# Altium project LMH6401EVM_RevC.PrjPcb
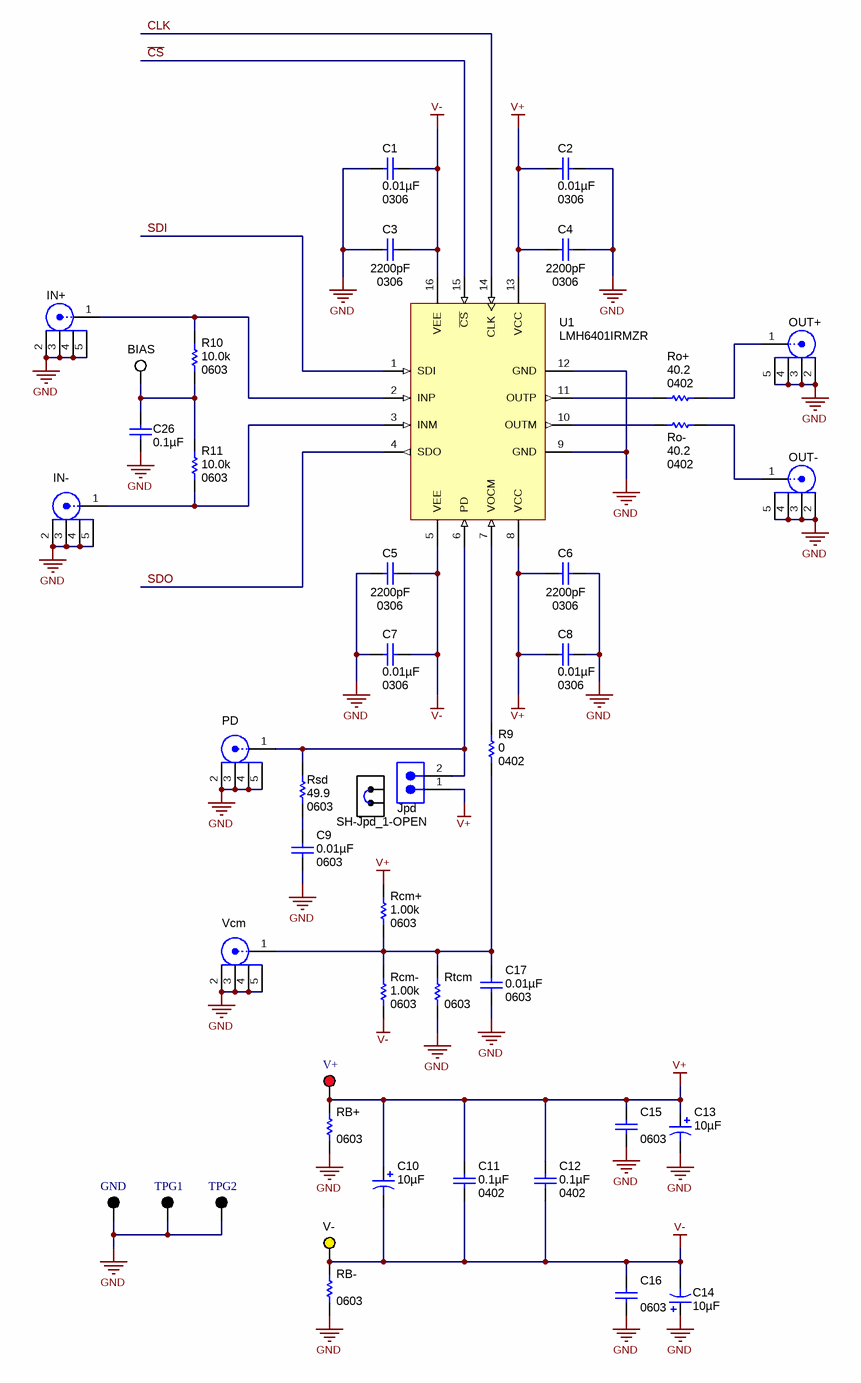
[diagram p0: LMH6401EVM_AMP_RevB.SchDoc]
CopyrightYear: 2018; PCB_Layout: Nick Oborny; PCB_Rev: A; PRJ_Customer: Public Release; PRJ_Engineer: Nick Oborny; PRJ_Number: MDBU014; PRJ_Title: DRV8305-Q1EVM; SCH_Rev: C; TechSupport: http://www.ti.com/support
2 sheets, 70 parts. Net scope: global (net labels, ports and power ports of the same name join across sheets).
Board file: LMH6401EVM.PcbDoc
Sheets:
  LMH6401EVM_AMP_RevB.SchDoc
  LMH6401EVM_Hardware_RevB.SchDoc

## Sheet LMH6401EVM_AMP_RevB.SchDoc
size 431 x 279 mm; Date: Not shown in title block; ApprovedBy: Not shown in title block; CheckedBy: Not shown in title block; Author: Not shown in title block; CompanyName: Not shown in title block; Engineer: Not shown in title block; Organization: Not shown in title block; Address1: Not shown in title block; Address2: Not shown in title block; Address3: Not shown in title block; Address4: Not shown in title block; DocumentNumber: 1; Revision: Use project parameter SCH_Rev; SheetNumber: 1; SheetTotal: 2; PageSetup: Record=PageOptions¦CenterHorizontal=True¦CenterVertical=True¦PrintScale=0.62¦XCorrection=1.00¦YCorrection=1.00¦PrintKind=0¦BorderSize=5000000¦LeftOffset=0¦BottomOffset=0¦Orientation=2¦PaperLength=1000¦PaperWidth=1000¦Scale=100¦PaperSource=15¦PrintQuality=600¦MediaType=1¦DitherType=10¦PaperKind=Letter¦PrintScaleMode=1

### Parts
BIAS  5012  [Keystone5012]  (value not drawn)
C1  ValueDisplayed: 0.01µF  [0306]  (hidden comment: LLL185R71E103MA01L)
C2  ValueDisplayed: 0.01µF  [0306]  (hidden comment: LLL185R71E103MA01L)
C3  ValueDisplayed: 2200pF  [0306]  (hidden comment: LLL185R71H222MA01L)
C4  ValueDisplayed: 2200pF  [0306]  (hidden comment: LLL185R71H222MA01L)
C5  ValueDisplayed: 2200pF  [0306]  (hidden comment: LLL185R71H222MA01L)
C6  ValueDisplayed: 2200pF  [0306]  (hidden comment: LLL185R71H222MA01L)
C7  ValueDisplayed: 0.01µF  [0306]  (hidden comment: LLL185R71E103MA01L)
C8  ValueDisplayed: 0.01µF  [0306]  (hidden comment: LLL185R71E103MA01L)
C9  ValueDisplayed: 0.01µF  PackageReference: 0603  [0603L]  (hidden comment: GRM188R71C103KA01D)
C10  ValueDisplayed: 10µF  [3216-18]  (hidden comment: TPSA106K010R0900)
C11  ValueDisplayed: 0.1µF  PackageReference: 0402  [0402L]  (hidden comment: C1005X5R1A104K)
C12  ValueDisplayed: 0.1µF  PackageReference: 0402  [0402L]  (hidden comment: C1005X5R1A104K)
C13  ValueDisplayed: 10µF  [3216-18]  (hidden comment: TPSA106K010R0900)
C14  ValueDisplayed: 10µF  [3216-18]  (hidden comment: TPSA106K010R0900)
C15  PackageReference: 0603  [0603L]  (hidden comment: Used in BOM report)
C16  PackageReference: 0603  [0603L]  (hidden comment: Used in BOM report)
C17  ValueDisplayed: 0.01µF  PackageReference: 0603  [0603L]  (hidden comment: GRM188R71C103KA01D)
C26  ValueDisplayed: 0.1µF  [0402L]  (hidden comment: C1005X5R1A104K)
GND  5011  [Keystone5011]  (value not drawn)
IN+  142-0701-851  [Emerson_142-0701-851]  (value not drawn)
IN-  142-0701-851  [Emerson_142-0701-851]  (value not drawn)
Jpd  TSW-102-07-G-S  [TSW-102-07-G-S]  (value not drawn)
OUT+  142-0701-851  [Emerson_142-0701-851]  (value not drawn)
OUT-  142-0701-851  [Emerson_142-0701-851]  (value not drawn)
PD  142-0701-851  [Emerson_142-0701-851]  (value not drawn)
R9  value 0  PackageReference: 0402  [0402L]  (hidden comment: ERJ-2GE0R00X)
R10  value 10.0k  PackageReference: 0603  [0603S]  (hidden comment: CRCW060310K0FKEA)
R11  value 10.0k  PackageReference: 0603  [0603S]  (hidden comment: CRCW060310K0FKEA)
RB+  PackageReference: 0603  [0603L]  (hidden comment: Used in BOM report)
RB-  PackageReference: 0603  [0603L]  (hidden comment: Used in BOM report)
Rcm+  value 1.00k  PackageReference: 0603  [0603L]  (hidden comment: CRCW06031K00FKEA)
Rcm-  value 1.00k  PackageReference: 0603  [0603L]  (hidden comment: CRCW06031K00FKEA)
Ro+  value 40.2  PackageReference: 0402  [0402L]  (hidden comment: CRCW040240R2FKED)
Ro-  value 40.2  PackageReference: 0402  [0402L]  (hidden comment: CRCW040240R2FKED)
Rsd  value 49.9  PackageReference: 0603  [0603L]  (hidden comment: CRCW060349R9FKEA)
Rtcm  PackageReference: 0603  [0603L]  (hidden comment: Used in BOM report)
SH-Jpd_1-OPEN  382811-6  (value not drawn)  (mechanical)
TPG1  5011  [Keystone5011]  (value not drawn)
TPG2  5011  [Keystone5011]  (value not drawn)
U1  LMH6401IRMZR  [RMZ0016A]
V+  5010  [Keystone5010]  (value not drawn)
V-  5014  [Keystone5014]  (value not drawn)
Vcm  142-0701-851  [Emerson_142-0701-851]  (value not drawn)

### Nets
GND: C1.1 C2.2 C3.2 C4.1 C5.2 C6.1 C7.1 C8.2 C9.2 C13.2(-) C14.1(+) C15.2 C16.2 C17.2 C26.1 GND.1 IN+.2 IN+.3 IN+.4 IN+.5 IN-.2 IN-.3 IN-.4 IN-.5 OUT+.2 OUT+.3 OUT+.4 OUT+.5 OUT-.2 OUT-.3 OUT-.4 OUT-.5 PD.2 PD.3 PD.4 PD.5 RB+.1 RB-.2 Rtcm.2 TPG1.1 TPG2.1 U1.9(GND) U1.12(GND) Vcm.2 Vcm.3 Vcm.4 Vcm.5
V+: C2.1 C4.2 C6.2 C8.1 C10.1(+) C11.2 C12.2 C13.1(+) C15.1 Jpd.1 RB+.2 Rcm+.2 U1.8(VCC) U1.13(VCC) V+.1
V-: C1.2 C3.1 C5.1 C7.2 C10.2(-) C11.1 C12.1 C14.2(-) C16.1 RB-.1 Rcm-.1 U1.5(VEE) U1.16(VEE) V-.1
~{CS}: U1.15(~{CS})
CLK: U1.14(CLK)
SDI: U1.1(SDI)
SDO: U1.4(SDO)
NetBIAS_1: BIAS.1 C26.2 R10.1 R11.2
NetC9_1: C9.1 Rsd.1
NetC17_1: C17.1 R9.1 Rcm+.1 Rcm-.2 Rtcm.1 Vcm.1
NetIN+_1: IN+.1 R10.2 U1.2(INP)
NetIN-_1: IN-.1 R11.1 U1.3(INM)
NetJpd_2: Jpd.2 PD.1 Rsd.2 U1.6(PD)
NetOUT+_1: OUT+.1 Ro+.2
NetOUT-_1: OUT-.1 Ro-.2
NetR9_2: R9.2 U1.7(VOCM)
NetRo+_1: Ro+.1 U1.11(OUTP)
NetRo-_1: Ro-.1 U1.10(OUTM)

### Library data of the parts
BIAS = 5012: Test Point, Multipurpose, White, TH; Manufacturer: Keystone; CompType: Test Point Loop; U/M: EA
C1 C2 C7 C8 = LLL185R71E103MA01L: CAP, CERM, 0.01uF, 25V, +/-20%, X7R, 0306; Manufacturer: MuRata; Polarized: N; CompType: Capacitor; U/M: EA; Cap_F: 0.00000001; Tolerance_%: 20; Value1: Unknown; VDC_V: 25; TaMin_C: -55; TaMax_C: 125
C3-C6 = LLL185R71H222MA01L: CAP, CERM, 2200pF, 50V, +/-20%, X7R, 0306; Manufacturer: MuRata; Polarized: N; CompType: Capacitor; U/M: EA; Cap_F: 0.0000000022; Tolerance_%: 20; Value1: Unknown; VDC_V: 50; TaMin_C: -55; TaMax_C: 125
C9 C17 = GRM188R71C103KA01D: CAP, CERM, 0.01uF, 16V, +/-10%, X7R, 0603; Manufacturer: MuRata; Polarized: N; CompType: Capacitor; U/M: EA; Cap_F: 0.00000001; Tolerance_%: 10; Value1: Unknown; VDC_V: 16; TaMin_C: -55; TaMax_C: 125
C10 C13 C14 = TPSA106K010R0900: CAP, TA, 10uF, 10V, +/-10%, 0.9 ohm, SMD; Manufacturer: AVX; Polarized: Y; CompType: Capacitor; U/M: EA; Cap_F: 0.00001; Tolerance_%: 10; Value1: 0.9 ohm; ESR_Ohm: 0.9; IRMS_A: 0.26; TaMin_C: -55; TaMax_C: 125; Cap_Case: A
C11 C12 = C1005X5R1A104K: CAP, CERM, 0.1uF, 10V, +/-10%, X5R, 0402; Manufacturer: TDK; Polarized: N; CompType: Capacitor; U/M: EA; Cap_F: 0.0000001; Tolerance_%: 10; ESR_Ohm: 0.0186; Value1: 0.0186 ohm; TaMin_C: -55; TaMax_C: 85
C15 C16 = Capacitor: CAP, CERM, xxxF, xxV, [TempCo], xx%, [PackageReference]; Polarized: N; U/M: EA
C26 = C1005X5R1A104K: CAP, CERM, 0.1uF, 10V, +/-10%, X5R, 0402; Manufacturer: TDK; Polarized: N; CompType: Capacitor; U/M: EA; Cap_F: 0.0000001; Tolerance_%: 10; ESR_Ohm: 0.0186; Value1: 0.0186 ohm; TaMin_C: -55; TaMax_C: 85; Cap_Case: 0402
GND TPG1 TPG2 = 5011: Test Point, TH, Multipurpose, Black; Manufacturer: Keystone Electronics; CompType: Test Point Loop
IN+ IN- OUT+ OUT- PD Vcm = 142-0701-851: Connector, SMT, End launch SMA 50 ohm; Manufacturer: Emerson Network Power; U/M: EA
Jpd = TSW-102-07-G-S: Header, TH, 100mil, 2x1, Gold plated, 230 mil above insulator; Manufacturer: Samtec, Inc.; U/M: EA
R9 = ERJ-2GE0R00X: RES, 0 ohm, 5%, 0.063W, 0402; Manufacturer: Panasonic; CompType: Resistor; Value_Code: 0000; Tolerance_%: 5; Power_W: 0.063; VDC_V: 50; TempCo: 600 ppm/C; EIA_Code: E24; U/M: EA
R10 R11 = CRCW060310K0FKEA: RES, 10.0k ohm, 1%, 0.1W, 0603; Manufacturer: Vishay-Dale; CompType: Resistor; Res_ohm: 10000; Value_Code: 10k0; Tolerance_%: 1; Power_W: 0.1; VDC_V: 75; TempCo: 100 ppm/C; EIA_Code: E96; U/M: EA
RB+ RB- Rtcm = Resistor: RES, xxx ohm, x%, xW, [PackageReference]; U/M: EA
Rcm+ Rcm- = CRCW06031K00FKEA: RES, 1.00k ohm, 1%, 0.1W, 0603; Manufacturer: Vishay-Dale; CompType: Resistor; Res_ohm: 1000; Value_Code: 1k00; Tolerance_%: 1; Power_W: 0.1; VDC_V: 75; TempCo: 100 ppm/C; EIA_Code: E96; U/M: EA
Ro+ Ro- = CRCW040240R2FKED: RES, 40.2 ohm, 1%, 0.063W, 0402; Manufacturer: Vishay-Dale; CompType: Resistor; Value_Code: 40R2; Tolerance_%: 1; Power_W: 0.063; VDC_V: 50; TempCo: 100 ppm/C; EIA_Code: E96; U/M: EA
Rsd = CRCW060349R9FKEA: RES, 49.9 ohm, 1%, 0.1W, 0603; Manufacturer: Vishay-Dale; CompType: Resistor; Value_Code: 49R9; Tolerance_%: 1; Power_W: 0.1; VDC_V: 75; TempCo: 100 ppm/C; EIA_Code: E96; U/M: EA
SH-Jpd_1-OPEN = 382811-6: Shunt, 100mil, Gold plated, Black; Manufacturer: AMP; Value: 1x2; Note: You can "mate" this to a header by matching the designator.  i.e. use SH-J3 for header J3
U1 = LMH6401IRMZR: 5 GHz Ultra Wideband Digital Variable Gain Amplifier, RMZ0016A; Alternate PartNumber: LMH6401IRMZT; Manufacturer: Texas Instruments; SymbolCreator: Altium; CompType: IC; U/M: EA
V+ = 5010: Test Point, TH, Multipurpose, Red; Manufacturer: Keystone Electronics; CompType: Test Point Loop
V- = 5014: Test Point, Multipurpose, Yellow, TH; Manufacturer: Keystone; CompType: Test Point Loop; U/M: EA

## Sheet LMH6401EVM_Hardware_RevB.SchDoc
size 431 x 279 mm; Date: Not shown in title block; ApprovedBy: Not shown in title block; CheckedBy: Not shown in title block; Author: Not shown in title block; CompanyName: Not shown in title block; Engineer: Not shown in title block; Organization: Not shown in title block; Address1: Not shown in title block; Address2: Not shown in title block; Address3: Not shown in title block; Address4: Not shown in title block; DocumentNumber: 2; Revision: Use project parameter SCH_Rev; SheetNumber: 2; SheetTotal: 2; PageSetup: Record=PageOptions|CenterHorizontal=True|CenterVertical=True|PrintScale=1.00|XCorrection=1.00|YCorrection=1.00|PrintKind=0|BorderSize=5000000|LeftOffset=0|BottomOffset=0|Orientation=2|PaperLength=1000|PaperWidth=1000|Scale=100|PaperSource=15|PrintQuality=600|MediaType=1|DitherType=10|PaperKind=Letter|PrintScaleMode=1
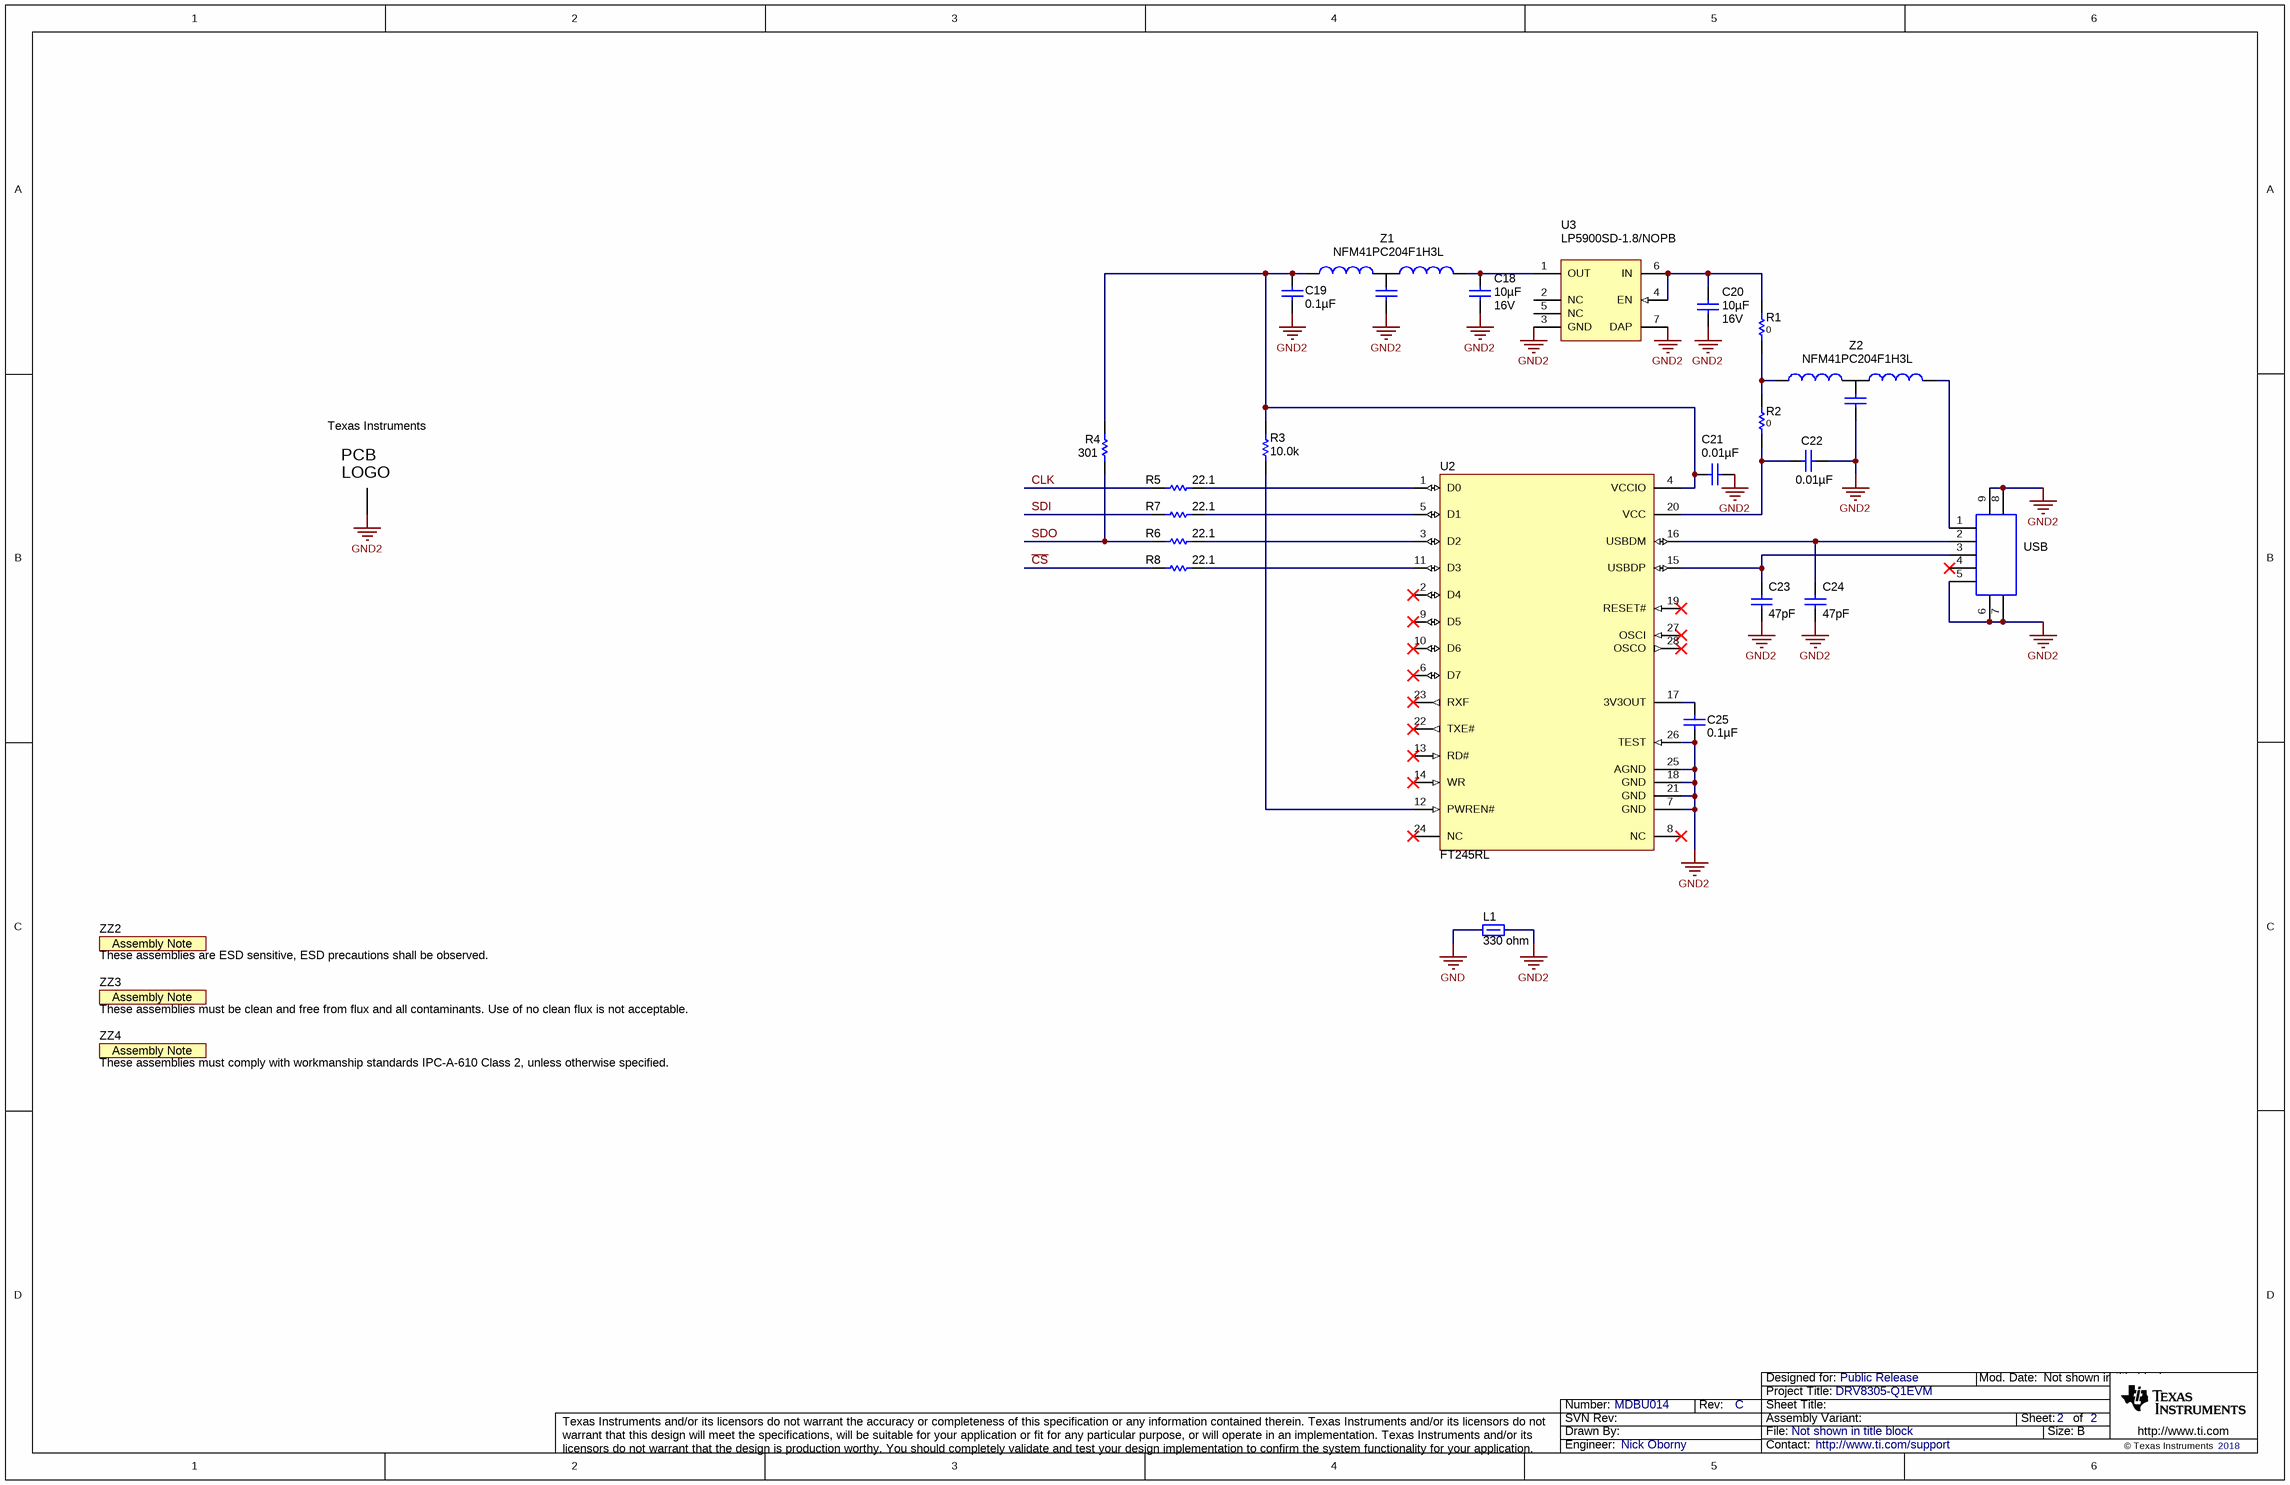
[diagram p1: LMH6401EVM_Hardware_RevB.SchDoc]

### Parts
C18  ValueDisplayed: 10µF  Value2: 16V  [0805L]  (hidden comment: EMK212BJ106KG-T)
C19  ValueDisplayed: 0.1µF  [0402L]  (hidden comment: C1005X5R1A104K)
C20  ValueDisplayed: 10µF  Value2: 16V  [0805L]  (hidden comment: EMK212BJ106KG-T)
C21  ValueDisplayed: 0.01µF  [0402L]  (hidden comment: C1005X7R1C103K)
C22  ValueDisplayed: 0.01µF  [0402L]  (hidden comment: C1005X7R1C103K)
C23  ValueDisplayed: 47pF  [0402L]  (hidden comment: GRM1555C1H470JZ01)
C24  ValueDisplayed: 47pF  [0402L]  (hidden comment: GRM1555C1H470JZ01)
C25  ValueDisplayed: 0.1µF  [0402L]  (hidden comment: C1005X5R1A104K)
L1  value 330 ohm  [0603]  (hidden comment: BLM18SG331TN1D)
Logo1  Texas Instruments  [TI_Stacked_SolderMask_Small_Vertical]  (no BOM)
R1  value 0  [0603L]  (hidden comment: CRCW06030000Z0EA)
R2  value 0  [0603L]  (hidden comment: CRCW06030000Z0EA)
R3  value 10.0k  [0402L]  (hidden comment: CRCW040210K0FKED)
R4  value 301  [0603L]  (hidden comment: CRCW0603301RFKEA)
R5  value 22.1  [0402L]  (hidden comment: CRCW040222R1FKED)
R6  value 22.1  [0402L]  (hidden comment: CRCW040222R1FKED)
R7  value 22.1  [0402L]  (hidden comment: CRCW040222R1FKED)
R8  value 22.1  [0402L]  (hidden comment: CRCW040222R1FKED)
U2  FT245RL  [SSOP28_N]
U3  LP5900SD-1.8/NOPB  [SDB06A]
USB  651-305-142-821  [CONN_USB-MINI-AB-651-305-142-821]  (value not drawn)
Z1  NFM41PC204F1H3L  [FIL_NFM41P]
Z2  NFM41PC204F1H3L  [FIL_NFM41P]
ZZ2  These assemblies are ESD sensitive, ESD precautions shall be observed.  [AssemblyNote]  (no BOM)
ZZ3  These assemblies must be clean and free from flux and all contaminants. Use of no clean flux is not acceptable.  [AssemblyNote]  (no BOM)
ZZ4  These assemblies must comply with workmanship standards IPC-A-610 Class 2, unless otherwise specified.  [AssemblyNote]  (no BOM)

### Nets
GND: L1.1
GND2: C18.2 C19.1 C20.2 C21.2 C22.2 C23.2 C24.2 C25.1 L1.2 Logo1.0 U2.7(GND) U2.18(GND) U2.21(GND) U2.25(AGND) U2.26(TEST) U3.3(GND) U3.7(DAP) USB.5 USB.6 USB.7 USB.8 USB.9 Z1.2 Z2.2
~{CS}: R8.1
CLK: R5.1
SDI: R7.1
SDO: R4.1 R6.1
NetC18_1: C18.1 U3.1(OUT) Z1.3
NetC19_2: C19.2 C21.1 R3.2 R4.2 U2.4(VCCIO) Z1.1
NetC20_1: C20.1 R1.1 U3.4(EN) U3.6(IN)
NetC22_1: C22.1 R2.2 U2.20(VCC)
NetC23_1: C23.1 U2.15(USBDP) USB.3
NetC24_1: C24.1 U2.16(USBDM) USB.2
NetC25_2: C25.2 U2.17(3V3OUT)
NetR1_2: R1.2 R2.1 Z2.1
NetR3_1: R3.1 U2.12(PWREN#)
NetR5_2: R5.2 U2.1(D0)
NetR6_2: R6.2 U2.3(D2)
NetR7_2: R7.2 U2.5(D1)
NetR8_2: R8.2 U2.11(D3)
NetUSB_1: USB.1 Z2.3

Not connected (* = marked no-connect by the designer): U2 2(D4)* 6(D7)* 8(NC)* 9(D5)* 10(D6)* 13(RD#)* 14(WR)* 19(RESET#)* 22(TXE#)* 23(RXF)* 24(NC)* 27(OSCI)* 28(OSCO)*; U3 2(NC) 5(NC); USB 4*

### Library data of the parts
C18 C20 = EMK212BJ106KG-T: CAP, CERM, 10uF, 16V, +/-10%, X5R, 0805; Manufacturer: Taiyo Yuden; Polarized: N; CompType: Capacitor; U/M: EA; Cap_F: 0.00001; Tolerance_%: 10; Value1: Unknown; VDC_V: 16; TaMin_C: -55; TaMax_C: 85; Cap_Case: 0805
C19 C25 = C1005X5R1A104K: as C26 on sheet LMH6401EVM_AMP_RevB
C21 C22 = C1005X7R1C103K: CAP, CERM, 0.01uF, 16V, +/-10%, X7R, 0402; Manufacturer: TDK; Polarized: N; CompType: Capacitor; U/M: EA; Cap_F: 0.00000001; Tolerance_%: 10; ESR_Ohm: 0.0623; Value1: 0.0623 ohm; VDC_V: 16; TaMin_C: -55; TaMax_C: 125; Cap_Case: 0402
C23 C24 = GRM1555C1H470JZ01: CAP, CERM, 47pF, 50V, +/-5%, C0G/NP0, 0402; Manufacturer: MuRata; Polarized: N; CompType: Capacitor; U/M: EA; Cap_F: 0.000000000047; Tolerance_%: 5; ESR_Ohm: 0.045; Value1: 0.045 ohm; VDC_V: 50; TaMin_C: -55; TaMax_C: 125; Cap_Case: 0402
L1 = BLM18SG331TN1D: 1.5A Ferrite Bead, 330 ohm @ 100MHz, SMD; Manufacturer: MuRata; Imax_A: 1.5; DCR_ohm: 0.07; Value1: 0.07 ohm; ZTyp@100MHz_Ohm: 330; U/M: EA
Logo1 = TI_Logo: Texas Instrument Corporate Signature; SymbolCreator: a0412235
R1 R2 = CRCW06030000Z0EA: RES, 0 ohm, 5%, 0.1W, 0603; Manufacturer: Vishay-Dale; CompType: Resistor; Tolerance_%: 5; VDC_V: 75; Power_W: 0.1; U/M: EA; Value_Code: 0000; EIA_Code: E24
R3 = CRCW040210K0FKED: RES, 10.0k ohm, 1%, 0.063W, 0402; Manufacturer: Vishay-Dale; CompType: Resistor; Res_ohm: 10000; Value_Code: 10k0; Tolerance_%: 1; Power_W: 0.063; VDC_V: 50; TempCo: 100 ppm/C; EIA_Code: E96; U/M: EA
R4 = CRCW0603301RFKEA: RES, 301 ohm, 1%, 0.1W, 0603; Manufacturer: Vishay-Dale; CompType: Resistor; Tolerance_%: 1; VDC_V: 75; Power_W: 0.1; Value_Code: 301R; EIA_Code: E96; U/M: EA
R5-R8 = CRCW040222R1FKED: RES, 22.1 ohm, 1%, 0.063W, 0402; Manufacturer: Vishay-Dale; CompType: Resistor; Value_Code: 22R1; Tolerance_%: 1; Power_W: 0.063; VDC_V: 50; TempCo: 100 ppm/C; EIA_Code: E96; U/M: EA
U2 = FT245RL: USB FIFO IC, 28SSOP; Manufacturer: FTDI; SymbolCreator: a0411947
U3 = LP5900SD-1.8/NOPB: Ultra Low Noise, 150mA Linear Regulator for RF/Analog Circuits Requires No Bypass Capacitor, 6-pin LLP, Pb-Free; Manufacturer: National Semiconductor; PackageTopMarking: XTT*L17; PowerWise: N; CompType: LDO IC
USB = 651-305-142-821: MINI USB 2.0 SMT TYPE AB 5 CONTACTS R/A, SMD; Manufacturer: Wurth Elektronik eiSos; SymbolCreator: a0799628; CompType: Connector; U/M: EA
Z1 Z2 = NFM41PC204F1H3L: Filter, LC, 0.2uF, 1806, SMT; Manufacturer: MuRata; SymbolCreator: a0799628
ZZ2-ZZ4 = AssemblyNote: SymbolCreator: codlsc

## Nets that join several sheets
GND: LMH6401EVM_AMP_RevB (47 pins), LMH6401EVM_Hardware_RevB (L1.1)
~{CS}: LMH6401EVM_AMP_RevB (U1.15), LMH6401EVM_Hardware_RevB (R8.1)
CLK: LMH6401EVM_AMP_RevB (U1.14), LMH6401EVM_Hardware_RevB (R5.1)
SDI: LMH6401EVM_AMP_RevB (U1.1), LMH6401EVM_Hardware_RevB (R7.1)
SDO: LMH6401EVM_AMP_RevB (U1.4), LMH6401EVM_Hardware_RevB (R4.1 R6.1)

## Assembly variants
001: not fitted C15 C16 R4 R10 R11 RB+ RB- Rtcm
